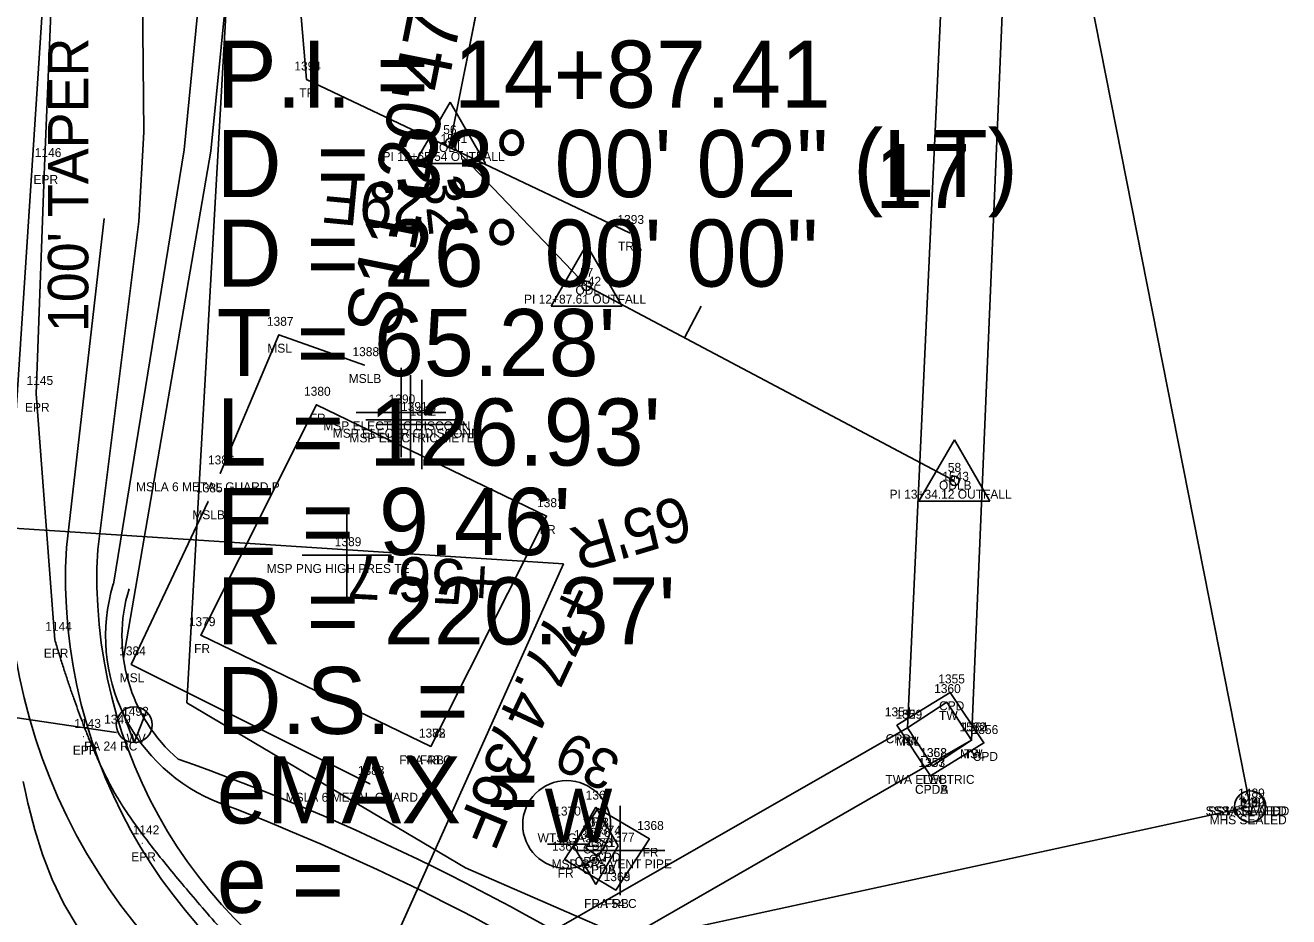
# Model space of a CAD drawing. Extents: x 1812113 to 1819860, y 1177290 to 1181185.
# Drawn here: x 1813680.6 to 1813821.8, y 1178765.6 to 1178865.2 of the extents above; entities that cross this region are included whole.
import ezdxf

# ---------------------------------------------------------------- set-up
doc = ezdxf.new("R2010")
doc.units = 0
for name, color, linetype in [('RD_EX_Conc', 7, 'Continuous'), ('RD_EX_Conc_txCode', 7, 'Continuous'), ('RD_EX_DR_Inlet', 7, 'Continuous'), ('RD_EX_DR_Pipe', 7, 'Continuous'), ('RD_EX_DR_Pipe_txCode', 7, 'Continuous'), ('RD_EX_DV_TX_Prop', 7, 'Continuous'), ('RD_EX_Fence_Other', 7, 'Continuous'), ('RD_EX_Fence_Other_txCode', 7, 'Continuous'), ('RD_EX_H2O', 7, 'Continuous'), ('RD_EX_H2O_txCode', 7, 'Continuous'), ('RD_EX_Misc', 7, 'Continuous'), ('RD_EX_Misc_txCode', 7, 'Continuous'), ('RD_EX_Road', 7, 'Continuous'), ('RD_EX_Road_txCode', 7, 'Continuous'), ('RD_EX_RW', 7, 'Continuous'), ('RD_EX_UT', 7, 'Continuous'), ('RD_EX_UT_txCode', 7, 'Continuous'), ('RD_EX_VEG', 7, 'Continuous'), ('RD_EX_VEG_txCode', 7, 'Continuous'), ('RD_HC_CL', 7, 'Continuous'), ('RD_HC_Data', 7, 'Continuous'), ('RD_HC_Data_Tic', 7, 'Continuous'), ('RD_HC_TX_StaOther', 7, 'Continuous'), ('RD_HC_txCode', 7, 'Continuous'), ('RD_PD_ALT1_TnTmp', 7, 'Continuous'), ('RD_PD_ALT1_TrvlWay', 7, 'Continuous'), ('RD_PD_ALT3_TnTmp', 7, 'Continuous'), ('RD_PD_CstnLmt', 7, 'Continuous'), ('RD_PD_DR_ErosCtrl', 7, 'Continuous'), ('RD_PD_Final_TnTmp', 7, 'Continuous'), ('RD_PD_GR', 7, 'Continuous'), ('RD_PD_PatLn1', 7, 'Continuous'), ('RD_Sketch7', 7, 'Continuous'), ('RD_Sketch8', 7, 'Continuous'), ('RD_SMD_Locator', 7, 'Continuous')]:
    doc.layers.add(name, color=color, linetype=linetype)

msp = doc.modelspace()

# ---------------------------------------------------------------- linework, layer by layer
at = {"layer": 'RD_EX_Conc'}
for points in [[(1813781.73, 1178781.31), (1813777.98, 1178786.97), (1813783.94, 1178790.65), (1813787.7, 1178784.99), (1813781.73, 1178781.31)], [(1813744.59, 1178772.35), (1813743.23, 1178773.25), (1813744.16, 1178774.64), (1813745.52, 1178773.74), (1813744.59, 1178772.35)]]:
    msp.add_lwpolyline(points, dxfattribs=at)
at = {"layer": 'RD_EX_DR_Inlet'}
for centre, radius in [((1813817.45, 1178777.9), 1.75), ((1813816.78, 1178778.53), 0.175), ((1813818.01, 1178778.46), 0.175), ((1813817.36, 1178777.24), 0.175)]:
    msp.add_circle(centre, radius, dxfattribs=at)
at = {"layer": 'RD_EX_DR_Pipe'}
msp.add_line((1813690.77, 1178786.15), (1813637.71, 1178794.06), dxfattribs=at)
at = {"layer": 'RD_EX_Fence_Other'}
for points in [[(1813725.93, 1178784.6), (1813700.22, 1178797.05), (1813713.13, 1178822.8), (1813738.84, 1178810.35), (1813725.93, 1178784.6)], [(1813746.59, 1178768.55), (1813740.84, 1178771.95), (1813744.58, 1178777.67), (1813750.33, 1178774.27), (1813746.59, 1178768.55)]]:
    msp.add_lwpolyline(points, dxfattribs=at)
at = {"layer": 'RD_EX_H2O'}
msp.add_lwpolyline([(1813697.92, 1178915.85), (1813709.32, 1178901.76), (1813721.45, 1178897.26), (1813733.34, 1178878.37), (1813728.06, 1178852.05), (1813743.31, 1178836.1), (1813784.4, 1178814.3)], dxfattribs=at)
at = {"layer": 'RD_EX_Misc'}
for p, q in [((1813722.59, 1178816.94), (1813722.59, 1178826.94)), ((1813723.66, 1178816.11), (1813723.66, 1178826.11)), ((1813724.9, 1178815.59), (1813724.9, 1178825.59)), ((1813717.59, 1178821.94), (1813727.59, 1178821.94)), ((1813718.66, 1178821.11), (1813728.66, 1178821.11)), ((1813719.9, 1178820.59), (1813729.9, 1178820.59)), ((1813716.53, 1178800.99), (1813716.53, 1178810.99)), ((1813711.53, 1178805.99), (1813721.53, 1178805.99)), ((1813747.06, 1178767.97), (1813747.06, 1178777.97)), ((1813742.06, 1178772.97), (1813752.06, 1178772.97))]:
    msp.add_line(p, q, dxfattribs=at)
for points in [[(1813405.71, 1178572.74), (1813779.17, 1178786.7), (1813799.35, 1179222.21)], [(1813408.47, 1178567.92), (1813786.33, 1178785.29), (1813804.76, 1179221.83)], [(1813702.39, 1178815.13), (1813708.94, 1178830.62), (1813718.51, 1178827.23)], [(1813719.11, 1178780.42), (1813692.45, 1178793.78), (1813701.04, 1178812)]]:
    msp.add_lwpolyline(points, dxfattribs=at)
at = {"layer": 'RD_EX_Road'}
for p, q in [((1813682.76, 1178849.48), (1813684.82, 1178900.28)), ((1813681.81, 1178824.01), (1813682.76, 1178849.48)), ((1813683.91, 1178796.53), (1813681.81, 1178824.01))]:
    msp.add_line(p, q, dxfattribs=at)
msp.add_open_spline([(1813706.04, 1178760.25), (1813693.68, 1178773.78), (1813687.15, 1178785.68), (1813683.91, 1178796.53)], degree=2, dxfattribs=at)
at = {"layer": 'RD_EX_RW'}
for p, q in [((1813698.67, 1178789.48), (1813713.48, 1179050.77)), ((1813698.67, 1178789.48), (1813729.8, 1178771.04)), ((1813729.8, 1178771.04), (1813768.43, 1178754.21))]:
    msp.add_line(p, q, dxfattribs=at)
at = {"layer": 'RD_EX_UT'}
for p, q in [((1813692.78, 1178785.04), (1813691.47, 1178788.52)), ((1813692.78, 1178785.04), (1813694.1, 1178788.49)), ((1813741.86, 1178773.5), (1813744.36, 1178777.83)), ((1813744.36, 1178777.83), (1813746.86, 1178773.5)), ((1813738.96, 1178773.67), (1813743.59, 1178773.67)), ((1813741.86, 1178773.5), (1813744.36, 1178769.17)), ((1813744.36, 1178769.17), (1813746.86, 1178773.5))]:
    msp.add_line(p, q, dxfattribs=at)
for points in [[(1813817.45, 1178777.9), (1813754.12, 1179098.9), (1813749.26, 1179176.64)], [(1813781.95, 1178782.42), (1813779.17, 1178786.7), (1813783.55, 1178789.57), (1813786.33, 1178785.29), (1813781.95, 1178782.42)], [(1813817.45, 1178777.9), (1813490.2, 1178706.76), (1813294.33, 1178669.42)]]:
    msp.add_lwpolyline(points, dxfattribs=at)
for centre, radius in [((1813692.78, 1178787.03), 2), ((1813741.09, 1178775.88), 4.91)]:
    msp.add_circle(centre, radius, dxfattribs=at)
at = {"layer": 'RD_EX_VEG'}
msp.add_lwpolyline([(1813748.11, 1178842.01), (1813712.02, 1178859.16), (1813709.48, 1178888.95), (1813708.93, 1178949.18), (1813715.24, 1179043.86)], dxfattribs=at)
at = {"layer": 'RD_HC_CL'}
for p, q in [((1813733.34, 1178878.37), (1813728.06, 1178852.05)), ((1813728.06, 1178852.05), (1813743.31, 1178836.1)), ((1813743.31, 1178836.1), (1813784.4, 1178814.3))]:
    msp.add_line(p, q, dxfattribs=at)
at = {"layer": 'RD_HC_Data'}
for p, q in [((1813724.09, 1178849.75), (1813728.06, 1178856.63)), ((1813728.06, 1178856.63), (1813732.03, 1178849.75)), ((1813724.09, 1178849.75), (1813732.03, 1178849.75)), ((1813739.34, 1178833.8), (1813743.31, 1178840.68)), ((1813743.31, 1178840.68), (1813747.28, 1178833.8)), ((1813739.34, 1178833.8), (1813747.28, 1178833.8)), ((1813780.43, 1178812.01), (1813784.4, 1178818.89)), ((1813784.4, 1178818.89), (1813788.37, 1178812.01)), ((1813780.43, 1178812.01), (1813788.37, 1178812.01))]:
    msp.add_line(p, q, dxfattribs=at)
for centre in [(1813728.06, 1178852.05), (1813743.31, 1178836.1), (1813784.4, 1178814.3)]:
    msp.add_circle(centre, 0.529, dxfattribs=at)
at = {"layer": 'RD_HC_Data_Tic'}
msp.add_line((1813754.26, 1178830.29), (1813756.13, 1178833.82), dxfattribs=at)
at = {"layer": 'RD_PD_ALT1_TrvlWay'}
msp.add_line((1813678.74, 1178809.04), (1813685.22, 1178908.83), dxfattribs=at)
msp.add_arc((1813743.64, 1178805.37), 65, 176.7565, 243.6045, dxfattribs=at)
at = {"layer": 'RD_PD_CstnLmt'}
for p, q in [((1813698.35, 1178851.3), (1813708.26, 1178950.9)), ((1813690.45, 1178802.75), (1813698.35, 1178851.3))]:
    msp.add_line(p, q, dxfattribs=at)
for centre, radius, start, end in [((1813709.58, 1178796.92), 20, 163.0681, 249.1681), ((1813611.44, 1178539), 255.97, 56.8168, 69.1681)]:
    msp.add_arc(centre, radius, start, end, dxfattribs=at)
at = {"layer": 'RD_PD_DR_ErosCtrl'}
for p, q in [((1813701.35, 1178851.13), (1813711.25, 1178950.73)), ((1813691.58, 1178794.47), (1813701.35, 1178851.13))]:
    msp.add_line(p, q, dxfattribs=at)
for centre, radius, start, end in [((1813709.58, 1178796.92), 18.17, 163.0681, 229.1504), ((1813611.44, 1178539), 258.97, 56.8421, 70.5446)]:
    msp.add_arc(centre, radius, start, end, dxfattribs=at)
at = {"layer": 'RD_PD_Final_TnTmp'}
for q in [(1813678.74, 1178809.04), (1813714.74, 1178747.14)]:
    msp.add_line((1813740.73, 1178805.02), q, dxfattribs=at)
at = {"layer": 'RD_PD_GR'}
msp.add_line((1813685.2, 1178806.83), (1813689.44, 1178843.6), dxfattribs=at)
msp.add_arc((1813743.64, 1178803.52), 58.53, 176.7565, 245.2829, dxfattribs=at)
at = {"layer": 'RD_PD_PatLn1'}
for p, q in [((1813693.85, 1178853.27), (1813693.3, 1178909.23)), ((1813693.29, 1178843.29), (1813693.85, 1178853.27)), ((1813688.7, 1178806.63), (1813693.29, 1178843.29))]:
    msp.add_line(p, q, dxfattribs=at)
msp.add_arc((1813743.64, 1178803.52), 55.03, 176.7565, 245.4118, dxfattribs=at)
at = {"layer": 'RD_Sketch7'}
for points in [[(1813680.91, 1178778.27), (1813680.66, 1178779.36), (1813680.38, 1178780.7)], [(1813686.52, 1178764.32), (1813684.92, 1178767), (1813683.62, 1178769.74), (1813682.55, 1178772.51), (1813681.68, 1178775.27), (1813680.97, 1178778), (1813680.91, 1178778.27)]]:
    msp.add_lwpolyline(points, dxfattribs=at)
msp.add_arc((1813706.29, 1178782.55), 35, 176.7565, 248.722, dxfattribs=at)
at = {"layer": 'RD_Sketch8'}
msp.add_arc((1813692.77, 1178773.67), 35, 176.7565, 250.8867, dxfattribs=at)
at = {"layer": 'RD_SMD_Locator'}
for centre in [(1813712.02, 1178859.16), (1813728.06, 1178852.05), (1813728.06, 1178852.05), (1813682.76, 1178849.48), (1813748.11, 1178842.01), (1813743.31, 1178836.1), (1813743.31, 1178836.1), (1813708.94, 1178830.62), (1813718.51, 1178827.23), (1813681.81, 1178824.01), (1813713.13, 1178822.8), (1813702.39, 1178815.13), (1813784.4, 1178814.3), (1813784.4, 1178814.3), (1813701.04, 1178812), (1813738.84, 1178810.35), (1813683.91, 1178796.53), (1813700.22, 1178797.05), (1813692.45, 1178793.78), (1813783.94, 1178790.65), (1813783.55, 1178789.57), (1813777.98, 1178786.97), (1813779.17, 1178786.7), (1813779.17, 1178786.7), (1813687.15, 1178785.68), (1813690.77, 1178786.15), (1813786.33, 1178785.29), (1813786.33, 1178785.29), (1813787.7, 1178784.99), (1813725.93, 1178784.6), (1813725.93, 1178784.6), (1813781.95, 1178782.42), (1813781.95, 1178782.42), (1813781.73, 1178781.31), (1813781.73, 1178781.31), (1813719.11, 1178780.42), (1813817.45, 1178777.9), (1813817.45, 1178777.9), (1813817.45, 1178777.9), (1813744.58, 1178777.67), (1813693.68, 1178773.78), (1813744.16, 1178774.64), (1813745.52, 1178773.74), (1813750.33, 1178774.27), (1813743.23, 1178773.25), (1813744.59, 1178772.35), (1813744.59, 1178772.35), (1813740.84, 1178771.95), (1813746.59, 1178768.55), (1813746.59, 1178768.55)]:
    msp.add_circle(centre, 0.001, dxfattribs=at)

# ---------------------------------------------------------------- texts
at = {"layer": 'RD_EX_Conc_txCode'}
for s, p in [('1355', (1813782.6, 1178791.65)), ('CPD', (1813782.69, 1178788.65)), ('1354', (1813776.63, 1178787.97)), ('1356', (1813786.33, 1178785.99)), ('CPD', (1813776.72, 1178784.97)), ('CPD', (1813786.45, 1178782.99)), ('1353', (1813780.39, 1178782.31)), ('1357', (1813780.39, 1178782.31)), ('CPDA', (1813779.99, 1178779.31)), ('CPDB', (1813780.01, 1178779.31)), ('1373', (1813742.82, 1178775.64)), ('1372', (1813741.89, 1178774.25)), ('1374', (1813744.18, 1178774.74)), ('CPD', (1813742.91, 1178772.64)), ('1375', (1813743.25, 1178773.35)), ('1371', (1813743.53, 1178773.35)), ('CPD', (1813741.98, 1178771.25)), ('CPD', (1813744.27, 1178771.74)), ('CPDA', (1813742.85, 1178770.35)), ('CPDB', (1813742.87, 1178770.35))]:
    msp.add_text(s, height=1, dxfattribs=at).set_placement(p)
at = {"layer": 'RD_EX_DR_Pipe_txCode'}
for s, p in [('1349', (1813689.42, 1178787.15)), ('PA 24 RC', (1813687.19, 1178784.15))]:
    msp.add_text(s, height=1, dxfattribs=at).set_placement(p)
at = {"layer": 'RD_EX_DV_TX_Prop'}
msp.add_text('17', height=7.14, dxfattribs=at).set_placement((1813775.55, 1178844.79))
at = {"layer": 'RD_EX_Fence_Other_txCode'}
for s, p in [('1380', (1813711.75, 1178823.8)), ('FR', (1813712.38, 1178820.8)), ('1381', (1813737.78, 1178811.35)), ('FR', (1813738.08, 1178808.35)), ('1379', (1813698.88, 1178798.05)), ('FR', (1813699.47, 1178795.05)), ('1378', (1813724.58, 1178785.6)), ('1382', (1813724.58, 1178785.6)), ('FRA 48 C', (1813722.38, 1178782.6)), ('FRB', (1813724.7, 1178782.6)), ('1367', (1813743.21, 1178778.67)), ('FR', (1813743.82, 1178775.67)), ('1368', (1813748.96, 1178775.27)), ('1366', (1813739.45, 1178772.95)), ('FR', (1813749.57, 1178772.27)), ('FR', (1813740.09, 1178769.95)), ('1365', (1813745.22, 1178769.55)), ('1369', (1813745.22, 1178769.55)), ('FRA 54 C', (1813743.04, 1178766.55)), ('FRB', (1813745.36, 1178766.55))]:
    msp.add_text(s, height=1, dxfattribs=at).set_placement(p)
at = {"layer": 'RD_EX_H2O_txCode'}
for s, p in [('1541', (1813727, 1178852.05)), ('ODL', (1813726.82, 1178851.05)), ('1542', (1813741.96, 1178836.1)), ('ODL', (1813742.07, 1178835.1)), ('1543', (1813783.05, 1178814.3)), ('ODLB', (1813782.68, 1178813.3))]:
    msp.add_text(s, height=1, dxfattribs=at).set_placement(p)
at = {"layer": 'RD_EX_Misc_txCode'}
for s, p in [('1387', (1813707.6, 1178831.62)), ('MSL', (1813707.65, 1178828.62)), ('1388', (1813717.16, 1178828.23)), ('MSLB', (1813716.74, 1178825.23)), ('1390', (1813721.2, 1178822.94)), ('1391', (1813722.59, 1178822.11)), ('1392', (1813723.55, 1178821.59)), ('MSP ELECTRIC DISCONN', (1813713.9, 1178819.94)), ('MSP ELECTRIC DISCONN', (1813714.96, 1178819.11)), ('MSP ELECTRIC METER', (1813716.83, 1178818.59)), ('1386', (1813701.02, 1178816.13)), ('MSLA 6 METAL GUARD P', (1813692.99, 1178813.13)), ('1385', (1813699.69, 1178813)), ('MSLB', (1813699.27, 1178810)), ('1389', (1813715.18, 1178806.99)), ('MSP PNG HIGH PRES TE', (1813707.57, 1178803.99)), ('1384', (1813691.1, 1178794.78)), ('MSL', (1813691.16, 1178791.78)), ('1529', (1813777.83, 1178787.7)), ('1532', (1813784.98, 1178786.29)), ('MSL', (1813777.88, 1178784.7)), ('MSL', (1813785.04, 1178783.29)), ('1383', (1813717.76, 1178781.42)), ('MSLA 6 METAL GUARD P', (1813709.7, 1178778.42)), ('1377', (1813745.71, 1178773.97)), ('MSP GAS VENT PIPE', (1813739.4, 1178770.97))]:
    msp.add_text(s, height=1, dxfattribs=at).set_placement(p)
at = {"layer": 'RD_EX_Road_txCode'}
for s, p in [('1146', (1813681.67, 1178850.48)), ('EPR', (1813681.53, 1178847.48)), ('1145', (1813680.75, 1178825.01)), ('EPR', (1813680.58, 1178822.01)), ('1144', (1813682.85, 1178797.53)), ('EPR', (1813682.68, 1178794.53)), ('1143', (1813686.09, 1178786.68)), ('EPR', (1813685.92, 1178783.68)), ('1142', (1813692.61, 1178774.78)), ('EPR', (1813692.45, 1178771.78))]:
    msp.add_text(s, height=1, dxfattribs=at).set_placement(p)
at = {"layer": 'RD_EX_UT'}
msp.add_text('W', height=6, dxfattribs=at).set_placement((1813738.62, 1178773.88))
at = {"layer": 'RD_EX_UT_txCode'}
for s, p in [('1360', (1813782.14, 1178790.57)), ('1493', (1813691.43, 1178788.03)), ('1359', (1813777.83, 1178787.7)), ('TW', (1813782.69, 1178787.57)), ('1361', (1813785.24, 1178786.29)), ('WV', (1813691.92, 1178785.03)), ('TW', (1813778.32, 1178784.7)), ('1362', (1813780.58, 1178783.42)), ('1358', (1813780.6, 1178783.42)), ('TW', (1813785.47, 1178783.29)), ('TWA ELECTRIC', (1813776.7, 1178780.42)), ('TWB', (1813780.62, 1178780.42)), ('1489', (1813816.1, 1178778.9)), ('1370', (1813739.7, 1178776.88)), ('SS2A SEALED', (1813812.46, 1178776.9)), ('SS1A SEALED', (1813812.75, 1178776.9)), ('SS SEALED', (1813813.42, 1178776.9)), ('1490', (1813816.06, 1178777.9)), ('1492', (1813816.1, 1178777.9)), ('1491', (1813816.39, 1178777.9)), ('MHS SEALED', (1813812.91, 1178775.9)), ('1376', (1813742.99, 1178774.5)), ('WTS GAS', (1813737.85, 1178773.88)), ('GV', (1813743.57, 1178771.5))]:
    msp.add_text(s, height=1, dxfattribs=at).set_placement(p)
at = {"layer": 'RD_EX_VEG_txCode'}
for s, p in [('1394', (1813710.67, 1178860.16)), ('TR', (1813711.22, 1178857.16)), ('1393', (1813746.76, 1178843.01)), ('TRA', (1813746.83, 1178840.01))]:
    msp.add_text(s, height=1, dxfattribs=at).set_placement(p)
at = {"layer": 'RD_HC_TX_StaOther'}
for s, p in [('P.I. = 14+87.41', (1813702, 1178856)), ('D', (1813702, 1178846)), ('    = 33%%d 00\' 02" (LT)', (1813702, 1178846)), ('D = 26%%d 00\' 00"', (1813702, 1178836)), ("T = 65.28'", (1813702, 1178826)), ("L = 126.93'", (1813702, 1178816)), ("E = 9.46'", (1813702, 1178806)), ("R = 220.37'", (1813702, 1178796)), ('D.S. = ', (1813702, 1178786)), ('eMAX = ', (1813702, 1178776)), ('e = ', (1813702, 1178766))]:
    msp.add_text(s, height=7.5, dxfattribs=at).set_placement(p)
at = {"layer": 'RD_HC_txCode'}
for s, p in [('56', (1813727.3, 1178853.05)), ('PI 12+65.54 OUTFALL', (1813720.52, 1178850.05)), ('57', (1813742.58, 1178837.1)), ('PI 12+87.61 OUTFALL', (1813736.33, 1178834.1)), ('58', (1813783.67, 1178815.3)), ('PI 13+34.12 OUTFALL', (1813777.16, 1178812.3))]:
    msp.add_text(s, height=1, dxfattribs=at).set_placement(p)
at = {"layer": 'RD_PD_ALT1_TnTmp'}
msp.add_text('S11%%d20\'47"W', height=6, rotation=78.6536, dxfattribs=at).set_placement((1813722.16, 1178830.14))
at = {"layer": 'RD_PD_ALT1_TrvlWay'}
msp.add_text("100' TAPER", height=4.5, rotation=90, dxfattribs=at).set_placement((1813687.65, 1178830.91))
at = {"layer": 'RD_PD_ALT3_TnTmp'}
for s, rotation, p in [("65'R", 196.711, (1813754.04, 1178812.76)), ('+56.7', 177.0321, (1813733.7, 1178805.27)), ('+77.47', 244.8579, (1813740.66, 1178803.31))]:
    msp.add_text(s, height=5, rotation=rotation, dxfattribs=at).set_placement(p)
at = {"layer": 'RD_PD_CstnLmt'}
for s, rotation, p in [('29F', 174.6218, (1813725.64, 1178847.08)), ('36F', 247.5268, (1813732.94, 1178785.53))]:
    msp.add_text(s, height=5, rotation=rotation, dxfattribs=at).set_placement(p)
at = {"layer": 'RD_PD_DR_ErosCtrl'}
for s, rotation, p in [('32', 276.3704, (1813725.02, 1178848.24)), ('39', 154.1875, (1813747.39, 1178783.47))]:
    msp.add_text(s, height=4.5, rotation=rotation, dxfattribs=at).set_placement(p)

doc.saveas('drawing.dxf')
